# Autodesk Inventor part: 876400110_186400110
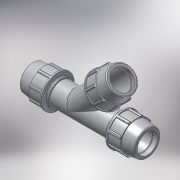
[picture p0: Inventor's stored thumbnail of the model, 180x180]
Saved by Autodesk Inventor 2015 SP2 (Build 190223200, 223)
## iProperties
Created: 2017-02
Part Number: 876400110_186400110
Material: PVC-Piping
Description: PLASSON 45° TEE 110-110-110
Document SubType Name: Modeling
Designer: KIM
Mass: 92.6774 g
Surface Area: 199.44 cm^2
Volume: 66.1981 cm^3
Density: 1.4 g/cm^3
Appearance: Smooth - White
Author: KIM
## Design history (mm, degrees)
derived "87640.ipt"
feature "Solid1::87640.ipt"
feature "Solid3::87640.ipt"
tag "TaggingFeature1"
body "Solid1"
other parameters: "d4" = 26.25, "d5" = 63, "d7" = 181, "d11" = 10.5, "d13" = 120 deg, "d14" = 143, "d15" = 8 deg, "d16" = 144.8, "d18" = 5.5, "d19" = 35 deg, "d20" = 17.5 deg, "d21" = 168.33, "d23" = 0, "d25" = 360 deg, "d27" = 3.62, "d33" = 2.2, "d42" = 75.6, "d43" = 5.43, "d46" = 3.3, "d68" = 9.45, "d91" = 126.7, "d93" = 196, "d95" = 99, "d134" = 315, "d138" = 45 deg, "d141" = 284, "d144" = 0, "d146" = 0, "d150" = 5.5, "d158" = 2.2, "d159" = 7.24, "d160" = 0, "d165" = 372.4, "d166" = 168.33, "d167" = 35 deg, "d168" = 17.5 deg, "d170" = 0, "d172" = 360 deg, "d174" = 5.43, "d177" = 3.62, "d180" = 7.24, "d181" = 0, "E_" = 181, "A_" = 284, "l_" = 196
